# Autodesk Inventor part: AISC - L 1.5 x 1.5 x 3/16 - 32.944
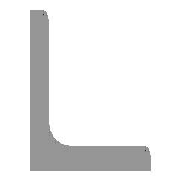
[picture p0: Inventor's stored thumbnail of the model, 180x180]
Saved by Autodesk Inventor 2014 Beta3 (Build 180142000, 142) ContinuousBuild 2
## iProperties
_CCFamilyMember: 5
_CCFamilyDisplayName: ANSI L (Equal angles) - Angle Steel
_FrameMemberDoc: Frame Member File
_Version: 15.0.0
_GetPNFromCC: 1
Created: 2010-11
Part Number: AISC - L 1.5 x 1.5 x 3/16 - 32.944
Material: Steel, Mild
Description: Angle Steel
Document SubType Name: Modeling
Standard: ANSI
Designer: Beta-8540w
Standards Organization: ANSI
Language: en-US
Size Designation: L 1.5 x 1.5 x 3/16
Categories: <MemberInstance><Categories><Category DisplayName="Structural Shapes" InternalName="089c4875-fa83-4c05-b084-43b9cc11f5ed" Mnemonic="GRDR"><CategoryParameter Dis
Stock Number: L 1.5 x 1.5 x 3/16
Density: 7.86 g/cm^3
Appearance: Steel
IsCustomPart: 1
G_L: 32.944 in
G_W: 1.500 in
G_H: 1.500 in
Author: Beta-8540w
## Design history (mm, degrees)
node "Start plane"
node "End plane"
sketch "Sketch"
  geometry: L1 (38.1, 0)-(0, 0); L2 (0, 0)-(0, 38.1); L3 (0, 38.1)-(2.476, 38.1); L4 (4.762, 35.814)-(4.762, 9.589); L5 (9.588, 4.763)-(35.814, 4.763); L6 (38.1, 2.477)-(38.1, 0); L7 (0, -11.041)-(0, 31.538); L8 (-11.041, 0)-(31.538, 0); L9 (0, 48.496)-(0, -20.964) reference; L10 (-20.964, 0)-(48.496, 0) reference; A1 r 4.826 centre (9.588, 9.589) between (4.762, 9.589) and (9.588, 4.763); A2 r 2.286 centre (2.476, 35.814) between (4.762, 35.814) and (2.476, 38.1); A3 r 2.286 centre (35.814, 2.477) between (38.1, 2.477) and (35.814, 4.763); 3 further points
  constraints: 16 end point, 6 point on circle, 6 point on line, 6 tangent, 4 parallel, 3 centre point, 2 collinear, 1 equal radius, 1 horizontal, 1 perpendicular
  dimensions: "d0" = 38.1 distance between parallel lines of L6 L2 (= G_H); "d1" = 38.1 distance between parallel lines of L3 L1 (= G_H); "d2" = 4.7625 distance between parallel lines of L2 L4 (= G_T); "d3" = 4.7625 distance between parallel lines of L1 L5 (= G_T); "d10" = 0 distance between parallel lines of L7 L2 (computed from ex); "d11" = 0 distance between parallel lines of L8 L1 (computed from d10); "d14" = 4.826 radius of A1 (= G_IR); "d15" = 2.286 radius of A2 (= G_ER)
extrude "Body" new body sketch "Sketch" stored distance "d4" = 836.76542 (= G_L); taper "d5" = 0 deg
node "Driven Length"
  sketch "Sketch3"
    geometry: L1 (0, 0)-(10, 0) reference
    constraints: 2 end point, 1 horizontal
  workplane "Work Plane3"
  sketch "Sketch4"
    geometry: L1 (-2, 0)-(12, 0) reference; L2 (-2, 836.765)-(12, 836.765) reference
    dimensions: "d17" = 836.76542 distance between parallel lines of L1 L2 (derived)
body "Solid1"
other parameters: "G_H" = 38.1 [user parameter; used in 2 equation terms], "G_T" = 4.7625 [user parameter; used in 2 equation terms], "G_ER" = 2.286 [user parameter; used in 1 equation term], "G_IR" = 4.826 [user parameter; used in 1 equation term], "G_L" = 836.76542 (= d17) [user parameter; used in 1 equation term], "ex" = 0 [user parameter; used in 1 equation term], "G_OFFSET_START" = 0 [user parameter; used in 1 equation term], "G_OFFSET_END" = 0 [user parameter; used in 1 equation term], "d12" = 0 (computed from G_OFFSET_START), "d13" = 836.76542 (= G_OFFSET_END + B_L), "B_L" = 836.76542 [user parameter; used in 1 equation term], "d16" = 90 deg, "MAS" = 0.26787 [user parameter]
